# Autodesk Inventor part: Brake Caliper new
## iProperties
Shininess: 78.0
Angle Display Precision: 2
Document Length Units: 11269
Document Angle Units: 11279
Document Time Units: 11290
Document Mass Units: 11283
Document Length Units Precision: 3
Document Angle Units Precision: 2
Compacted: True
Created: 2001-10
Part Number: Brake Caliper new
Document SubType Name: Modeling
Designer: Martin Budgell
Density: 0.0
Volumn: 0.0
Area: 0.0
PropertySet Name: Model Information
Control State: 0
Master: False
Checked Out: False
Author: Martin Budgell
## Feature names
1. Extrusion1
2. Extrusion2
3. Mirror1
4. Extrusion3
5. Mirror2
6. Revolution1
7. Extrusion4
8. Fillet1
9. Fillet2
10. Fillet3
11. Fillet4
12. Fillet5
13. Extrusion5
14. Fillet6
15. Fillet7
16. TaperEdge1
17. TaperEdge2
18. Fillet8
19. Fillet9
20. Extrusion6
21. Extrusion7
22. Extrusion8
23. Extrusion9
24. Fillet10
25. Hole1
26. Hole2
27. Extrusion10
28. Fillet11
29. Extrusion11
30. Extrusion12
